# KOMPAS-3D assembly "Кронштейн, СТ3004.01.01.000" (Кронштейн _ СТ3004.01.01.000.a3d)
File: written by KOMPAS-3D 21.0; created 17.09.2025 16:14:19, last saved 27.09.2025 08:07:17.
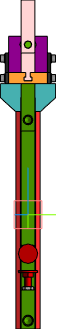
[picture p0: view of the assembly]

Document properties: Полное имя файла: C:\Users\Lutik\Yandex.Disk\Документы\Новая папка\Стапель №2\Стапель _ СТ3004.00.00.000\Опора _ СТ3004.01.00.000\3D\Кронштейн _ СТ3004.01.01.000\Кронштейн _ СТ3004.01.01.000.a3d; Автор: 1

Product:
- Part/product: Кронштейн  | designation СТ3004.01.01.000
    Масса: 11.762936
    Форматы листов документа: A2
  - Component [standard]: Винт М8-6gx25.56.019 ГОСТ 11738-84  | qty 8  | pos. 11  | Материал: Сталь 30 ГОСТ 1050-2013 (density 1000 kg/m3); Масса: 0.01513; Раздел спецификации: Стандартные изделия; Рассекать на разрезах: no
  - Component [standard]: Винт М6-6gx20.56.019 ГОСТ 11738-84  | qty 6  | pos. 10  | Материал: Сталь 30 ГОСТ 1050-2013 (density 1000 kg/m3); Масса: 0.00666; Раздел спецификации: Стандартные изделия; Рассекать на разрезах: no
  - Component [standard]: Шайба A.8.01.10.019 ГОСТ 11371-78  | qty 6  | pos. 12  | Масса: 0.001828; Раздел спецификации: Стандартные изделия; Рассекать на разрезах: no
  - Component [detail]: Косынка  | designation СТ3003.01.01.002  | qty 2  | pos. 3  | Материал: Лист$dБ-ПН-НО-6 ГОСТ 19903-2015;Ст3сп ГОСТ 14637-89$ (density 7850 kg/m3); Масса: 0.116828; Форматы листов документа: A4; source file: ..\..\..\..\Стапель _ СТ3003.00.00.000\Опора _ СТ3003.01.00.000\3D\Кронштейн _ СТ3003.01.01.000\Косынка _ СТ3003.01.01.002.m3d
  - Component [detail]: Упор  | designation СТ3004.01.01.001  | pos. 8  | Материал: Сталь 45  ГОСТ 1050-2013 (density 7810 kg/m3); Масса: 1.534235; Форматы листов документа: A3; source file: ..\..\2D\Кронштейн _ СТ3004.01.01.000\Упор _ СТ3004.01.01.001.cdw, Упор _ СТ3004.01.01.001.m3d
  - Component [detail]: Винт  | designation СТ3003.01.01.001  | pos. 2  | Материал: Круг$d30 ГОСТ 2590-2006;Ст3сп ГОСТ 535-2005$ (density 7850 kg/m3); Масса: 0.311599; Форматы листов документа: A4; additional columns: 110; source file: ..\..\..\..\Стапель _ СТ3003.00.00.000\Опора _ СТ3003.01.00.000\2D\Кронштейн _ СТ3003.01.01.000\Винт _ СТ3003.01.01.001.cdw, ..\..\..\..\Стапель _ СТ3003.00.00.000\Опора _ СТ3003.01.00.000\3D\Кронштейн _ СТ3003.01.01.000\Винт _ СТ3003.01.01.001.m3d
  - Component [detail]: Опора  | designation СТ3003.01.01.004  | qty 2  | pos. 5  | Материал: Круг$d35 ГОСТ 2590-2006;Ст3сп ГОСТ 535-2005$ (density 7850 kg/m3); Масса: 0.078797; Форматы листов документа: A4; source file: ..\..\..\..\Стапель _ СТ3003.00.00.000\Опора _ СТ3003.01.00.000\2D\Кронштейн _ СТ3003.01.01.000\Опора _ СТ3003.01.01.004.cdw, ..\..\..\..\Стапель _ СТ3003.00.00.000\Опора _ СТ3003.01.00.000\3D\Кронштейн _ СТ3003.01.01.000\Опора _ СТ3003.01.01.004.m3d
  - Component [detail]: Планка  | designation СТ3003.01.01.005  | pos. 6  | Материал: Сталь 45  ГОСТ 1050-2013 (density 7810 kg/m3); Масса: 1.670176; Форматы листов документа: A3; source file: ..\..\..\..\Стапель _ СТ3003.00.00.000\Опора _ СТ3003.01.00.000\2D\Кронштейн _ СТ3003.01.01.000\Планка _ СТ3003.01.01.005.cdw, ..\..\..\..\Стапель _ СТ3003.00.00.000\Опора _ СТ3003.01.00.000\3D\Кронштейн _ СТ3003.01.01.000\Планка _ СТ3003.01.01.005.m3d
  - Component [detail]: Пластина  | designation СТ3003.01.01.006  | pos. 7  | Материал: Лист$dБ-ПН-НО-16 ГОСТ 19903-2015;Ст3сп ГОСТ 14637-89$ (density 7850 kg/m3); Масса: 0.669577; Форматы листов документа: A4; source file: ..\..\..\..\Стапель _ СТ3003.00.00.000\Опора _ СТ3003.01.00.000\3D\Кронштейн _ СТ3003.01.01.000\Пластина _ СТ3003.01.01.006.m3d
  - Component [detail]: Направляющая  | designation СТ3003.01.01.003  | pos. 4  | Материал: Сталь 45  ГОСТ 1050-2013 (density 7810 kg/m3); Масса: 0.806848; Форматы листов документа: A3; source file: ..\..\..\..\Стапель _ СТ3003.00.00.000\Опора _ СТ3003.01.00.000\3D\Кронштейн _ СТ3003.01.01.000\Направляющая _ СТ3003.01.01.003.m3d
  - Component [assembly]: Основание  | designation СТ3004.01.01.100  | pos. 1  | Масса: 6.204975; Форматы листов документа: A3; source file: ..\..\2D\Кронштейн _ СТ3004.01.01.000\Основание _ СТ3004.01.01.100\Основание _ СТ3004.01.01.100.cdw, Основание _ СТ3004.01.01.100\Основание _ СТ3004.01.01.100.a3d
  - Component [standard]: Гайка шестигранная низкая ГОСТ ISO 4035-М12-05-A2P  | qty 2  | pos. 13  | Материал: Сталь (density 1000 kg/m3); Масса: 0.001154; Раздел спецификации: Стандартные изделия; Рассекать на разрезах: no; additional columns: M12 - 05 - A2P

Referenced files in C:\Users\1\Yandex.Disk\Документы\Новая папка\Стапель №2\Стапель _ СТ3003.00.00.000\Опора _ СТ3003.01.00.000\3D\Кронштейн _ СТ3003.01.01.000\: Направляющая _ СТ3003.01.01.003.m3d, Косынка _ СТ3003.01.01.002.m3d, Пластина _ СТ3003.01.01.006.m3d, Винт _ СТ3003.01.01.001.m3d, Опора _ СТ3003.01.01.004.m3d, Планка _ СТ3003.01.01.005.m3d
Referenced files in C:\Users\1\Yandex.Disk\Документы\Новая папка\Стапель №2\Стапель _ СТ3004.00.00.000\Опора _ СТ3004.01.00.000\3D\Кронштейн _ СТ3004.01.01.000\Основание _ СТ3004.01.01.100\: Основание _ СТ3004.01.01.100.a3d
Referenced files in C:\Users\Lutik\Yandex.Disk\Документы\Новая папка\Стапель №2\Стапель _ СТ3004.00.00.000\Опора _ СТ3004.01.00.000\3D\Кронштейн _ СТ3004.01.01.000\: Упор _ СТ3004.01.01.001.m3d
Referenced files in C:\Users\Lutik\Yandex.Disk\Документы\Новая папка\Стапель №2\Стапель _ СТ3004.00.00.000\Опора _ СТ3004.01.00.000\3D\Кронштейн _ СТ3004.01.01.000\Основание _ СТ3004.01.01.100\: Основание _ СТ3004.01.01.100.a3d
Referenced files in C:\Users\Lutik\Yandex.Disk\Документы\Новая папка\Стапель №2\Стапель _ СТ3004.00.00.000\Опора _ СТ3004.01.00.000\2D\Кронштейн _ СТ3004.01.01.000\Основание _ СТ3004.01.01.100\: Основание _ СТ3004.01.01.100.cdw
Referenced files in C:\Users\Lutik\Yandex.Disk\Документы\Новая папка\Стапель №2\Стапель _ СТ3003.00.00.000\Опора _ СТ3003.01.00.000\3D\Кронштейн _ СТ3003.01.01.000\: Направляющая _ СТ3003.01.01.003.m3d, Косынка _ СТ3003.01.01.002.m3d, Пластина _ СТ3003.01.01.006.m3d, Планка _ СТ3003.01.01.005.m3d, Опора _ СТ3003.01.01.004.m3d, Винт _ СТ3003.01.01.001.m3d
Referenced files in C:\Users\Lutik\Yandex.Disk\Документы\Новая папка\Стапель №2\Стапель _ СТ3003.00.00.000\Опора _ СТ3003.01.00.000\2D\Кронштейн _ СТ3003.01.01.000\: Планка _ СТ3003.01.01.005.cdw, Опора _ СТ3003.01.01.004.cdw, Винт _ СТ3003.01.01.001.cdw
Referenced files in C:\Users\Lutik\Yandex.Disk\Документы\Новая папка\Стапель №2\Стапель _ СТ3004.00.00.000\Опора _ СТ3004.01.00.000\2D\Кронштейн _ СТ3004.01.01.000\: Упор _ СТ3004.01.01.001.cdw
Referenced files in C:\Program Files\ASCON\KOMPAS-3D v21\Libs\PARTLib\DATA\vault\Methods\Kompas\3D\: PLib_Washer_1_712.m3d, PLib_Nut_ISO_1100.m3d
Referenced files in C:\Program Files\ASCON\KOMPAS-3D v21\Libs\PartLib\DATA\VAULT\Methods\Kompas\3D\: PLib_Screw_GOST_11738_1500.m3d
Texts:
  СТ3003.01.01.003
  СТ3003.01.01.002
  СТ3003.01.01.006
  СТ3003.01.01.001
  СТ3004.01.01.100
  СТ3003.01.01.004
  СТ3003.01.01.005
  СТ3004.01.01.001
  Крепежное изделие ГОСТ
  Гайка шестигранная низкая
  СТ3004.01.01.000
  bcut1
  hole1
  hcut1
  r1pt
  hole2
  cut1
  cut2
